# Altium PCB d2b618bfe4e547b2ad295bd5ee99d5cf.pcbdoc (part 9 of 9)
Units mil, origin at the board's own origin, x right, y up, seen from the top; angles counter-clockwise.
Board outline 5129 x 4161 mil, 8 copper layers (Top Layer, GND1, 内层2, VCC, 内层4, Inner5, GND2, Bottom Layer); 491 components, 452 nets, 2562 pads, 1124 vias.
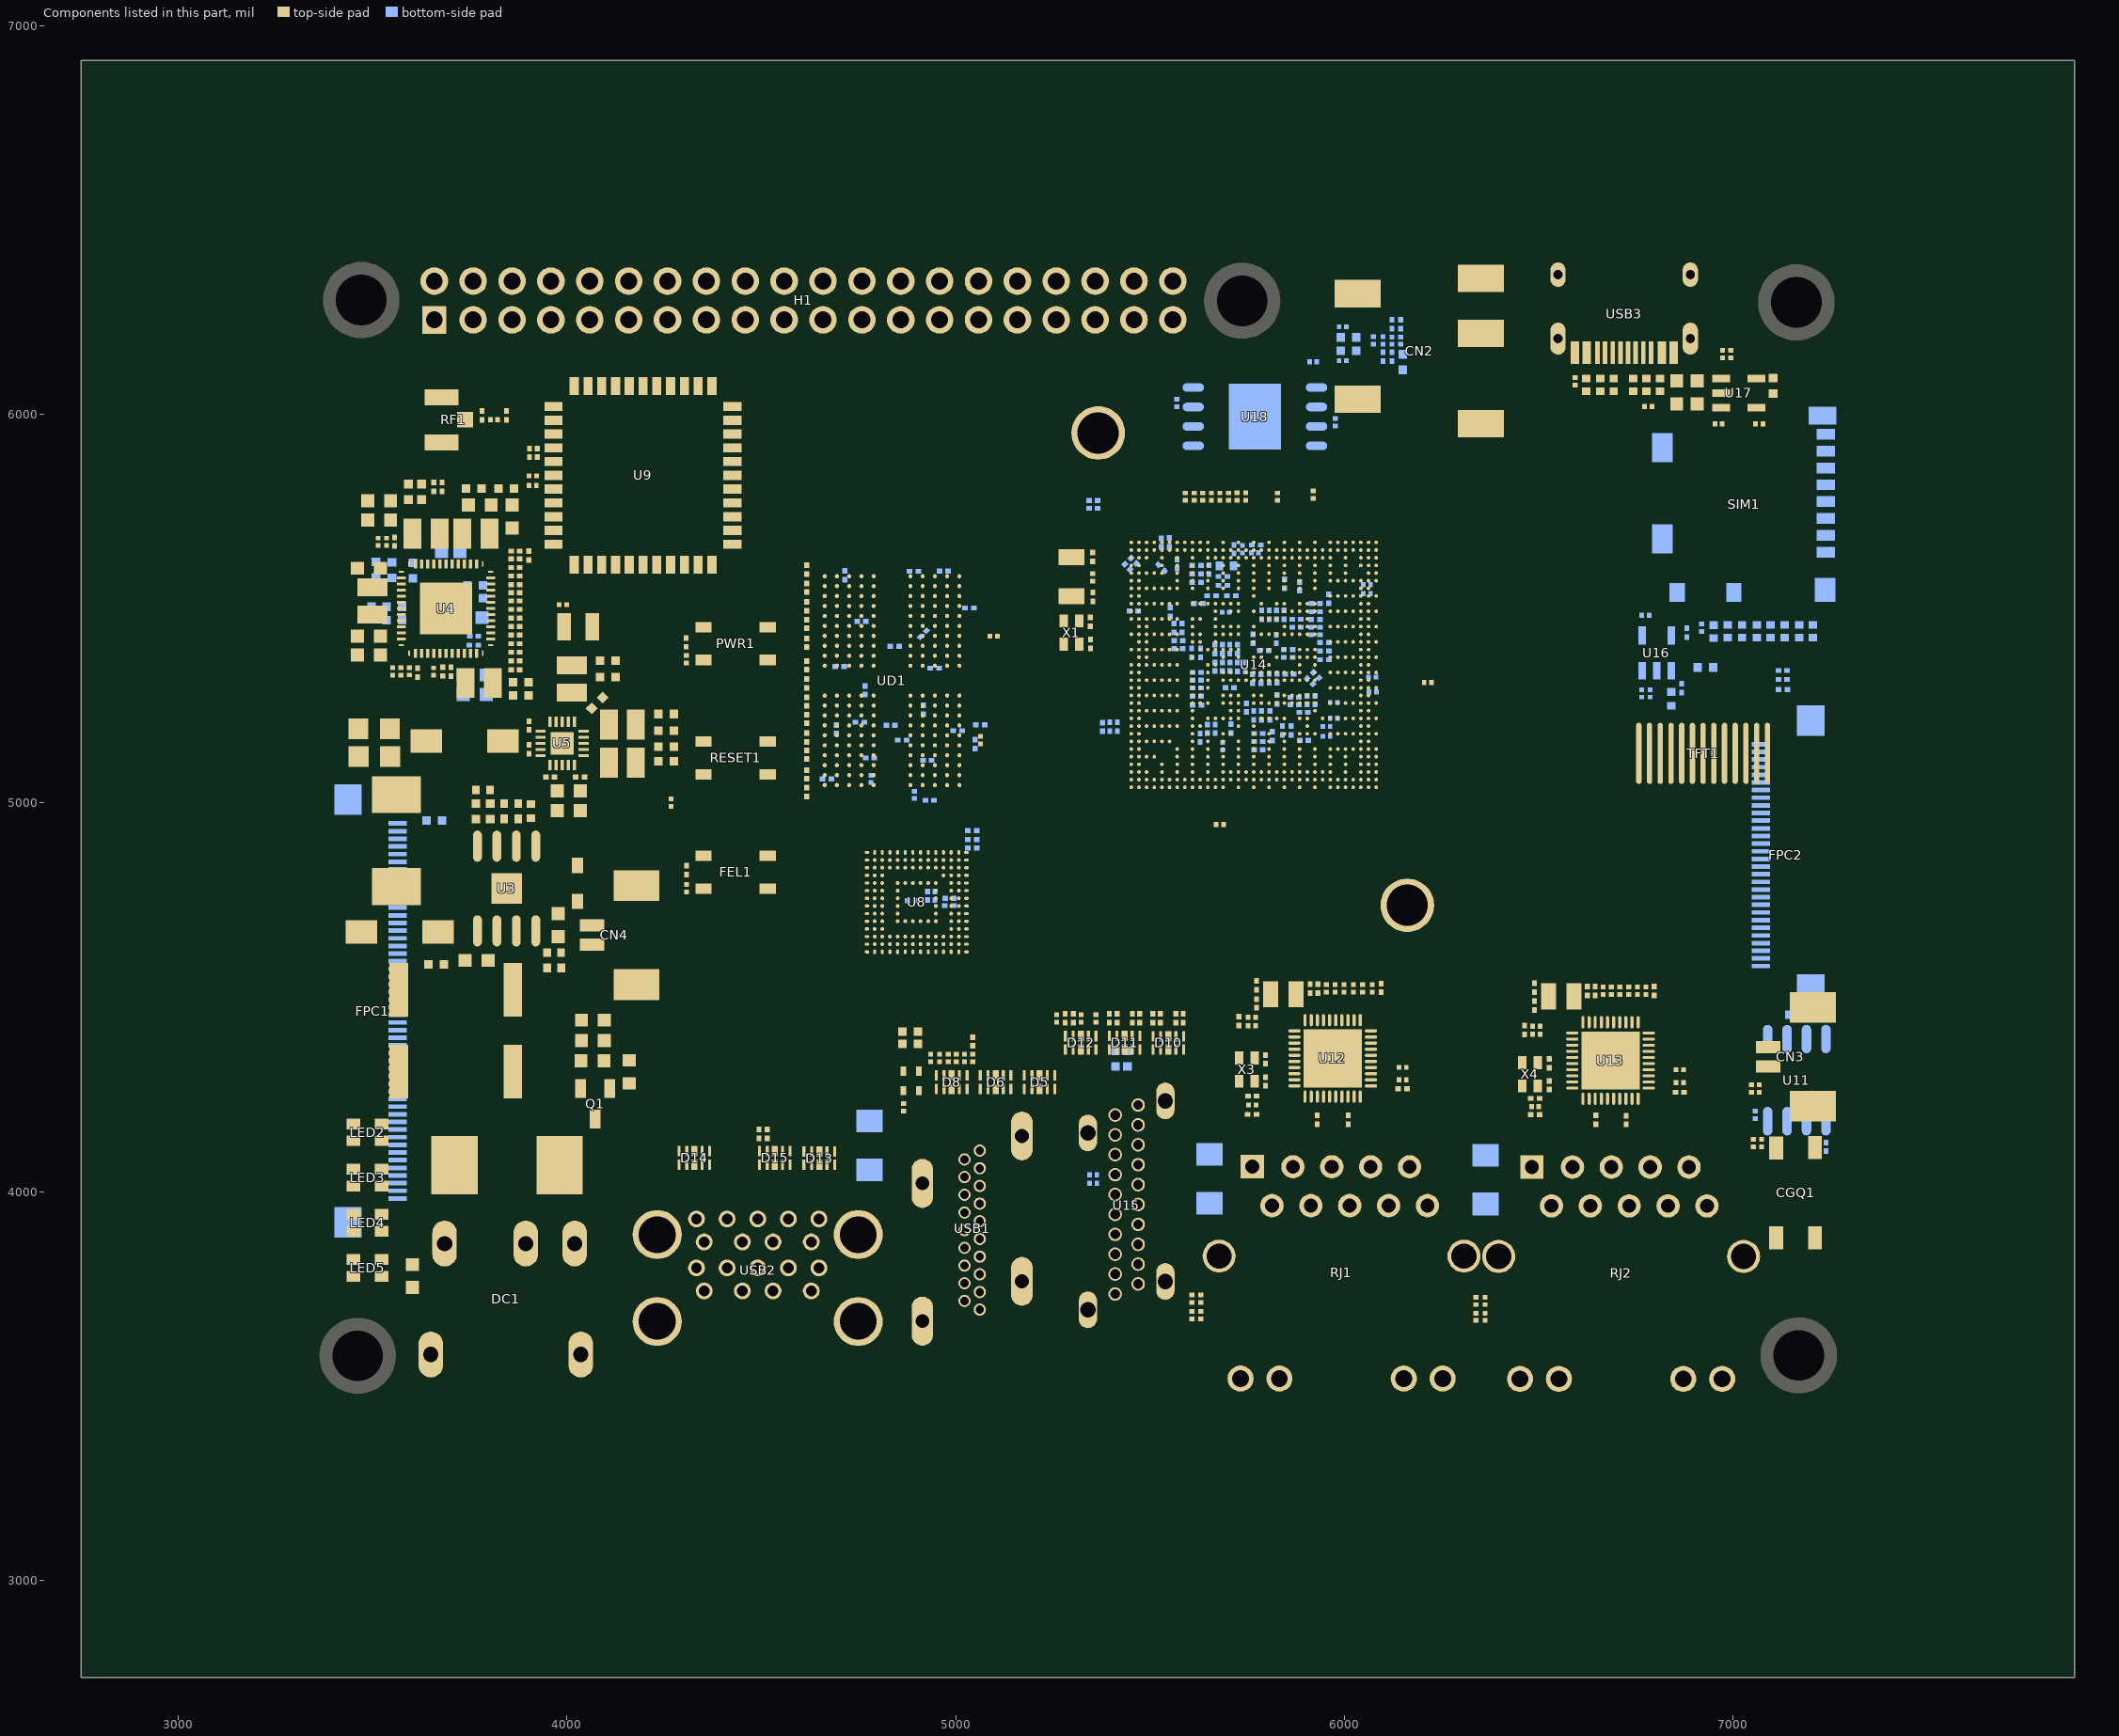
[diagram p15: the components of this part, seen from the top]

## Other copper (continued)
Inner5:
  region net VBUS: 3631.83,6301.69 3617.69,6315.83 3622.19,6322.33 3623.66,6329.06 3623.62,6344.97 3660.97,6307.62 3645.06,6307.66 3638.33,6306.19
  region net VBUS: 3707.43,6353 3707.43,6333 3699.65,6331.59 3693.85,6327.87 3682.62,6316.59 3682.62,6369.41 3693.85,6358.13 3699.65,6354.41
  region net PE15: 3792.43,6199.4 3779.91,6206.26 3777.51,6208.71 3774.15,6209.9 3765.57,6209.84 3756.16,6208.76 3747.92,6209.34 3793.68,6235.73 3789.24,6216.96 3789.17,6208.36
  region net VBUS: 3710.57,6333 3710.57,6353 3718.35,6354.41 3724.15,6358.13 3735.38,6369.41 3735.38,6316.59 3724.15,6327.87 3718.35,6331.59
  region net PE14: 3894.66,6210.17 3891.83,6207.34 3884.94,6210.05 3875.43,6209.72 3857.03,6207.62 3894.38,6244.97 3892.28,6226.57 3891.95,6217.06
  region net PE11: 3994.66,6210.17 3991.83,6207.34 3984.94,6210.05 3975.43,6209.72 3957.03,6207.62 3994.38,6244.97 3992.28,6226.57 3991.95,6217.06
  region net PE13: 4193.94,6205.89 4187.38,6206.79 4184.58,6208.9 4180.86,6209.89 4171.72,6209.61 4161.93,6208.22 4153.51,6208 4194.4,6241.43 4192.48,6230.52 4189.81,6222.22 4189.32,6214.64
  region net PE0: 4194.66,6310.17 4191.83,6307.34 4184.94,6310.05 4175.43,6309.72 4157.03,6307.62 4194.38,6344.97 4192.28,6326.57 4191.95,6317.06
  region net PE2: 4294.66,6210.17 4291.83,6207.34 4284.94,6210.05 4275.43,6209.72 4257.03,6207.62 4294.38,6244.97 4292.28,6226.57 4291.95,6217.06
  region net PE4: 4393.24,6202.59 4383.7,6206.47 4381.08,6208.76 4377.54,6209.85 4368.68,6209.66 4359.08,6208.39 4350.71,6208.55 4394.16,6238.59 4389.56,6219.58 4389.28,6211.52
  region net PE3: 4334.98,6316.15 4332.15,6318.98 4333.62,6321.58 4333.48,6324.49 4330.12,6330.98 4325.65,6337.97 4323.62,6344.97 4360.97,6307.62 4353.97,6309.65 4346.98,6314.12 4340.49,6317.48 4337.58,6317.62
  region net PE9: 4427.93,6307.1 4423.61,6308.44 4426.15,6315.44 4425.81,6325.11 4423.57,6343.56 4462.38,6307.73 4444.05,6309.65 4434.68,6309.97
  region net PE10: 4994.66,6210.17 4991.83,6207.34 4984.94,6210.05 4975.43,6209.72 4957.03,6207.62 4994.38,6244.97 4992.28,6226.57 4991.95,6217.06
  region net SDQ30: 4873.68,5531.22 4873.68,5526.72 4870.66,5525.59 4868.17,5523.11 4868.17,5534.84 4870.66,5532.36
  region net SDQ28: 4832.17,5447.21 4827.67,5447.21 4826.54,5450.23 4824.05,5452.73 4835.79,5452.73 4833.3,5450.23
  region net SDQ29: 4688.04,5459.96 4684.86,5456.77 4681.92,5458.11 4678.4,5458.11 4686.7,5466.41 4686.71,5462.89
  region net SCS0-B: 4892.9,5383.77 4889.72,5386.96 4891.05,5389.89 4891.06,5393.41 4899.36,5385.11 4895.83,5385.11
  region net SCS1-B: 4948.51,5384.38 4949.54,5391.78 4951.26,5393.84 4952.53,5396.58 4955.05,5385.12 4951.89,5385.51
  region net SCKE0-B: 4887.88,5359.26 4889.63,5367.37 4891.43,5369.31 4892.82,5371.96 4894.44,5360.5 4891.27,5360.35
  region net SCKE1-B: 4858.16,5363.72 4858.16,5368.22 4861.17,5369.36 4863.67,5371.84 4863.67,5360.11 4861.17,5362.59
  region net SDQM3: 5199.72,5346.99 5202.9,5350.17 5205.83,5348.84 5209.36,5348.84 5201.06,5340.54 5201.05,5344.06
  region net SDQS3P: 5258.47,5321.47 5254.47,5326.47 5259.98,5330.39 5263.98,5319.35 5261.24,5321.19
  region net SAB4: 4760.12,5309.96 4756.94,5306.77 4754,5308.11 4750.48,5308.11 4758.78,5316.41 4758.79,5312.89
  region net SDQ28: 5199.75,5323.62 5202.53,5327.2 5205.55,5325.93 5209.07,5325.95 5201.19,5317.26 5201.14,5320.78
  region net SCKE0-B: 5113.15,5312.71 5113.15,5317.21 5116.16,5318.35 5118.66,5320.83 5118.66,5309.1 5116.16,5311.58
  region net SDQS3N: 5258.87,5310.71 5262.4,5314.24 5267.24,5314.34 5259.33,5305.66
  region net SAB5: 4695.51,5301.38 4692.33,5304.57 4692.52,5306.84 4692.06,5309.41 4700.36,5301.11 4697.78,5301.58
  region net SDQ27: 5481.85,5303.82 5485.03,5307 5487.96,5305.67 5491.49,5305.67 5483.19,5297.37 5483.18,5300.89
  region net SDQ24: 5571.71,5305.93 5576.21,5305.93 5577.68,5304.32 5579.83,5302.96 5568.09,5302.96 5570.24,5304.32
  region net SDQ26: 5503.11,5305.6 5507.95,5307.12 5510.48,5305.57 5513.95,5305.33 5504.17,5298.85
  region net SDQ25: 5544.57,5307.14 5550.9,5307.18 5553.32,5305.71 5556.34,5304.82 5545.52,5300.29 5545.67,5303.73
  region net SCKE1-B: 5138.03,5291.68 5136.75,5299.32 5140.28,5297.99 5143.55,5298.33 5141.01,5286.87 5139.74,5289.62
  region net SAA5: 4720.94,5300.17 4724.12,5296.99 4722.79,5294.06 4722.78,5290.54 4714.48,5298.84 4718,5298.84
  region net SDQ29: 5480.29,5256.18 5480.29,5260.68 5483.3,5261.82 5485.8,5264.3 5485.8,5252.57 5483.3,5255.05
  region net SDQ31: 5544.41,5267.3 5550.27,5267.8 5552.81,5266.42 5555.91,5265.65 5545.37,5260.46
  region net SDQ30: 5502.76,5264.36 5505.94,5267.54 5508.87,5266.21 5512.4,5266.21 5504.1,5257.91 5504.09,5261.43
  region net SAA4: 4707.67,5252.74 4712.17,5252.74 4713.3,5249.72 4715.79,5247.22 4704.05,5247.22 4706.54,5249.72
  region net SAA2: 4784.39,5238.22 4780.31,5233.72 4777.55,5232.97 4774.8,5231.39 4778.88,5242.39
  region net SAA1: 5103.92,5206.61 5100.74,5203.42 5095.8,5203.1 5103.75,5211.73
  region net SDQ25: 4841.12,5603.96 4837.94,5600.77 4835,5602.11 4831.48,5602.11 4839.78,5610.41 4839.79,5606.89
  region net SDQ24: 4780.05,5579.22 4784.52,5574.72 4781.33,5573.1 4779.01,5570.55 4774.53,5581.4 4777.3,5579.9
  region net SDQ27: 4718.51,5541.57 4715.33,5538.38 4712.7,5539.41 4709.48,5539.11 4717.78,5547.41 4717.48,5544.19
  region net SCS1-A: 4973.68,5191.22 4973.68,5186.72 4970.66,5185.59 4968.17,5183.11 4968.17,5194.84 4970.66,5192.36
  region net SAA0: 5121.68,5184.22 5121.68,5179.72 5118.66,5178.59 5116.17,5176.11 5116.17,5187.84 5118.66,5185.36
  region net SDQ8: 5654.21,5145.98 5654.21,5150.48 5657.22,5151.62 5659.72,5154.1 5659.72,5142.37 5657.22,5144.85
  region net SAB4: 5525.37,5132.3 5523.25,5134.43 5524.45,5137.56 5524.06,5141.41 5532.36,5133.11 5528.5,5133.51
  region net SCS1-B: 5516.41,5146.27 5519.59,5143.09 5518.37,5138.44 5512.83,5148.61 5514.66,5147.07
  region net SCS0-B: 5480.69,5140.02 5478.59,5148.48 5482,5147.37 5485.14,5147.23 5484.12,5135.65 5482.58,5138.19
  region net SDQ14: 5700.2,5130.05 5697.02,5133.24 5698.35,5136.17 5698.36,5139.69 5706.66,5131.39 5703.13,5131.39
  region net SDQ15: 4721.68,5166.22 4721.68,5161.72 4718.66,5160.59 4716.17,5158.11 4716.17,5169.84 4718.66,5167.36
  region net SDQ14: 4690.99,5154.17 4687.89,5150.91 4684.94,5152.23 4681.42,5152.23 4689.63,5160.61 4689.65,5157.09
  region net SDQS1N: 4720.4,5128.9 4715.4,5122.97 4713.96,5126.36 4711.51,5128.48 4721.63,5134.41
  region net SDQS1P: 4731.16,5129.19 4729.28,5134.38 4731.9,5139.55 4736.14,5128.61
  region net SDQ8: 4840.94,5157.17 4844.12,5153.99 4842.79,5151.06 4842.78,5147.54 4834.48,5155.84 4838,5155.84
  region net SCS1-A: 5112.33,5149.07 5114.37,5144.75 5112.88,5142.38 5111.93,5139.4 5107.69,5150.34 5110.01,5149.13
  region net SDQ9: 5663.35,5118.23 5655.76,5117 5657.08,5120.52 5656.75,5123.81 5668.19,5121.19 5665.43,5119.93
  region net SAA4: 5518.64,5119.47 5520.89,5122.47 5523.73,5123.88 5526.4,5126.23 5524.15,5114.71 5521.78,5117.71
  region net SAA2: 5543.68,5110.62 5543.05,5114.23 5544.05,5117.26 5544.26,5120.82 5550.94,5111.16 5547.13,5111.61
  region net SDQ9: 4863.67,5119.47 4868.17,5119.47 4869.64,5117.72 4871.79,5116.22 4860.05,5116.22 4862.2,5117.72
  region net SDQM1: 4832.33,5115.38 4835.51,5118.57 4837.78,5118.37 4840.36,5118.84 4832.06,5110.54 4832.52,5113.11
  region net SAB5: 5480.3,5097.98 5480.3,5102.48 5483.31,5103.62 5485.81,5106.1 5485.81,5094.37 5483.31,5096.85
  region net SAA1: 5504.74,5091.82 5502.78,5094.09 5504.22,5097.13 5504.11,5101 5511.77,5092.1 5507.95,5092.79
  region net SDQ10: 5658.62,5090.5 5657.41,5095.65 5659,5098.1 5659.3,5101.54 5665.4,5091.51
  region net SAA5: 5558.42,5107.66 5559.36,5102.24 5557.74,5099.86 5557.37,5096.43 5551.61,5106.66
  region net SDQM1: 5622.9,5070.77 5619.72,5073.96 5621.05,5076.89 5621.06,5080.41 5629.36,5072.11 5625.83,5072.11
  region net SAA0: 5499.98,5073.72 5495.51,5078.22 5498.69,5079.85 5501.02,5082.4 5505.49,5071.55 5502.72,5073.05
  region net SDQ11: 5669.1,5067.49 5664.6,5067.49 5663.47,5070.51 5660.98,5073.01 5672.72,5073.01 5670.23,5070.51
  region net SDQ10: 4836.67,5066.47 4841.17,5066.47 4842.3,5064.09 4844.79,5062.22 4833.05,5062.22 4835.54,5064.09
  region net SDQ11: 4875.68,5059.22 4875.68,5054.72 4872.66,5053.59 4870.17,5051.11 4870.17,5062.84 4872.66,5060.36
  region net SDQ12: 5700.92,5020.22 5700.92,5015.72 5698.11,5014.59 5695.83,5012.11 5695.83,5023.84 5698.11,5021.36
  region net SDQS1N: 5680.42,4981.89 5675.42,4984.88 5674.93,4987.72 5672.91,4990.39 5684.26,4987.41
  region net SDQS1P: 5667.55,4991.38 5664.65,4987.21 5662.37,4987.36 5659.97,4986.37 5665.24,4996.86 5665.82,4993.6
  region net SDQ13: 5704.94,4983.83 5696.11,4981.36 5697.24,4984.79 5697.38,4987.89 5709.06,4987.51 5706.64,4985.83
  region net SDQ13: 4696.17,5015.21 4691.67,5015.21 4690.54,5018.23 4688.05,5020.73 4699.79,5020.73 4697.3,5018.23
  region net SDQ12: 4668.12,5019.96 4664.94,5016.77 4662,5018.11 4658.48,5018.11 4666.78,5026.41 4666.79,5022.89
  region net SDQS3P: 4755.29,5518.97 4747.42,5513.97 4744.63,5514.41 4741.52,5514.11 4749.78,5522.42 4752.05,5520.48
  region net SDQM3: 4720.12,5513.96 4716.94,5510.77 4714,5512.11 4710.48,5512.11 4718.78,5520.41 4718.79,5516.89
  region net SDQ31: 4833.67,5523.97 4838.17,5523.97 4841.79,5520.22 4830.05,5520.22
  region net SDQ26: 4699.72,5501.99 4702.9,5505.17 4705.83,5503.84 4709.36,5503.84 4701.06,5495.54 4701.05,5499.06
  region net SDQS3N: 4741,5504.59 4746.68,5503.21 4747.14,5498.11 4736,5501.8
  region net SDQ15: 5698.66,5151.53 5698.46,5157.69 5699.89,5160.16 5700.74,5163.21 5705.5,5152.48
  region net VDD-CPULFB: 3764.93,5349.86 3757.86,5356.93 3760.05,5358.93 3761.14,5361.44 3769.44,5353.14 3766.93,5352.05
  region net AP-WAKE-BT: 5776.22,5609.39 5776.22,5613.39 5779.25,5614.59 5781.73,5617.25 5781.73,5605.52 5779.25,5608.18
  region net BT-WAKE-AP: 5793.18,5600.71 5796,5597.88 5794.71,5594.88 5794.84,5591.25 5786.54,5599.55 5790.18,5599.42
  region net UART1-CTS: 5793.18,5581.04 5796,5578.21 5794.71,5575.21 5794.84,5571.58 5786.54,5579.88 5790.18,5579.75
  region net UART1-TX: 5832.55,5581.04 5835.38,5578.21 5834.09,5575.21 5834.21,5571.58 5825.91,5579.88 5829.55,5579.75
  region net UART1-RX: 5832.55,5600.71 5835.38,5597.88 5834.09,5594.88 5834.21,5591.25 5825.91,5599.55 5829.55,5599.42
  region net UART1-RTS: 5824.34,5622.14 5828.34,5622.14 5829.55,5619.11 5832.21,5616.63 5820.48,5616.63 5823.14,5619.11
  region net PE15: 5876.99,5559.81 5874.82,5551.99 5873.08,5549.99 5871.75,5547.26 5870.24,5558.76 5873.51,5558.82
  region net PE14: 5896.06,5558.52 5898.89,5561.34 5901.89,5560.05 5905.53,5560.18 5897.23,5551.88 5897.35,5555.52
  region net PE11: 5935.26,5556.91 5936.76,5561.07 5940.03,5559.98 5943.64,5560.15 5936.77,5550.63 5936.72,5554.24
  region net PE13: 5973.08,5590 5973.07,5594 5976.1,5595.21 5978.58,5597.87 5978.59,5586.13 5976.11,5588.79
  region net PE2: 6014.01,5612.4 6012.51,5619.55 6016.01,5618.18 6019.27,5618.51 6016.68,5607.28 6015.6,5610.19
  region net PE3: 6021.2,5642.14 6025.2,5642.14 6026.41,5639.11 6029.07,5636.63 6017.33,5636.63 6019.99,5639.11
  region net PE0: 6015,5590 6015,5594 6016.51,5595.57 6017.75,5597.87 6017.75,5586.13 6016.51,5588.43
  region net HSDA: 6009.04,5207.67 6012.57,5204.14 6011.2,5201.27 6011.06,5197.86 6002.76,5206.16 6006.17,5206.3
  region net HSCL: 6032.46,5198.07 6033.25,5190.21 6029.83,5191.62 6026.62,5191.37 6029.37,5202.78
  region net HHPD: 6033.65,5161.43 6033.65,5156.43 6030.65,5155.38 6028.14,5153.06 6028.14,5164.8 6030.65,5162.48
  region net HCEC: 6012.58,5153.09 6009.04,5149.56 6006.18,5150.93 6002.77,5151.07 6011.07,5159.37 6011.21,5155.95
  region net LCD0-D13: 5989.5,5073.02 5984.5,5066.8 5983.08,5070.23 5980.63,5072.31 5990.59,5078.53
  region net LCD0-D12: 5972.11,5091.57 5973.34,5099.88 5976.62,5104.39 5978.47,5093 5975.39,5092.75
  region net LCD0-HSYNC: 5910.93,5148.31 5914.47,5144.77 5913.09,5141.91 5912.95,5138.49 5904.65,5146.79 5908.07,5146.93
  region net LCD0-D20: 5957.81,5135.5 5949.92,5130.5 5944.41,5130.37 5952.3,5138.96 5954.59,5137
  region net PE10: 6113.8,5757.98 6110.98,5760.8 6112.27,5763.8 6112.14,5767.44 6120.44,5759.14 6116.8,5759.27
  region net PE9: 6134.8,5757.98 6131.98,5760.8 6133.27,5763.8 6133.14,5767.44 6141.44,5759.14 6137.8,5759.27
  region net PE4: 6156.8,5757.98 6153.98,5760.8 6155.27,5763.8 6155.14,5767.44 6163.44,5759.14 6159.8,5759.27
  region net HHPD: 5102.76,4420.5 5102.76,4415.5 5099.76,4414.45 5097.25,4412.13 5097.25,4423.87 5099.76,4421.55
  region net HSDA: 5012.76,4374.5 5012.76,4369.5 5009.76,4368.45 5007.25,4366.13 5007.25,4377.87 5009.76,4375.55
  region net HSCL: 4964.84,4379.38 4968.38,4375.84 4967,4372.98 4966.86,4369.56 4958.56,4377.86 4961.98,4378
  region net HCEC: 4942.84,4379.38 4946.38,4375.84 4945,4372.98 4944.86,4369.56 4936.56,4377.86 4939.98,4378
  region net MCSI0-D2N: 5992.22,5466.7 5989.39,5463.88 5986.39,5465.16 5982.76,5465.04 5991.06,5473.34 5990.93,5469.7
  region net MCSI0-D2P: 6006,5465 6002,5465 6000.43,5466.51 5998.13,5467.75 6009.87,5467.75 6007.57,5466.51
  region net MCSI0-D3N: 6011.41,5507.41 6008.59,5504.59 6005.89,5505.57 6002.56,5505.14 6010.86,5513.44 6010.43,5510.11
  region net MCSI0-D3P: 6018.41,5505.59 6015.59,5508.41 6015.72,5510.77 6015.14,5513.44 6023.44,5505.14 6020.77,5505.72
  region net MCSI0-SCK: 6010.93,5540.9 6003.75,5542.43 6001.58,5544.04 5998.7,5545.18 6010.12,5547.89 6009.72,5544.5
  region net MCSI0-SDA: 6032.64,5553.64 6032.64,5549.64 6030.11,5548.43 6028.14,5545.77 6028.14,5557.5 6030.11,5554.84
  region net CTP-SDA: 5812.16,4850.62 5808.62,4854.16 5810,4857.02 5810.14,4860.44 5818.44,4852.14 5815.02,4852
  region net CTP-SCK: 5821.24,4873.5 5821.24,4878.5 5824.24,4879.55 5826.75,4881.87 5826.75,4870.13 5824.24,4872.45
  region net CTP-INT: 5831.24,4891.5 5831.24,4896.5 5834.24,4897.55 5836.75,4899.87 5836.75,4888.13 5834.24,4890.45
  region net LCD0-D17: 5840.24,4909.5 5840.24,4914.5 5843.24,4915.55 5845.75,4917.87 5845.75,4906.13 5843.24,4908.45
  region net LCD0-D10: 4630.76,4675.5 4630.76,4670.5 4627.76,4669.45 4625.25,4667.13 4625.25,4678.87 4627.76,4676.55
  region net LCD0-D11: 4648.76,4659.5 4648.76,4654.5 4645.76,4653.45 4643.25,4651.13 4643.25,4662.87 4645.76,4660.55
  region net LCD0-D12: 4664.76,4643.5 4664.76,4638.5 4661.76,4637.45 4659.25,4635.13 4659.25,4646.87 4661.76,4644.55
  region net LCD0-D13: 4679.76,4626.5 4679.76,4621.5 4676.76,4620.45 4674.25,4618.13 4674.25,4629.87 4676.76,4627.55
  region net LCD0-D14: 4697.76,4610.5 4697.76,4605.5 4694.76,4604.45 4692.25,4602.13 4692.25,4613.87 4694.76,4611.55
  region net LCD0-D15: 4709.76,4592.5 4709.76,4587.5 4706.76,4586.45 4704.25,4584.13 4704.25,4595.87 4706.76,4593.55
  region net LCD0-D15: 5964.5,4905.24 5959.5,4905.24 5958.45,4908.24 5956.13,4910.75 5967.87,4910.75 5965.55,4908.24
  region net LCD0-D14: 5965.67,4932.5 5973.21,4937.5 5978.73,4937.87 5971.19,4929.02 5968.88,4931.01
  region net LCD0-D10: 5836.24,4817.5 5836.24,4822.5 5839.24,4823.55 5841.75,4825.87 5841.75,4814.13 5839.24,4816.45
  region net LCD0-D11: 5867.5,4824.24 5862.5,4824.24 5861.45,4827.24 5859.13,4829.75 5870.87,4829.75 5868.55,4827.24
  region net LCD0-D19: 4537.76,4525.5 4537.76,4520.5 4534.76,4519.45 4532.25,4517.13 4532.25,4528.87 4534.76,4526.55
  region net LCD0-D20: 4552.76,4506.5 4552.76,4501.5 4549.76,4500.45 4547.25,4498.13 4547.25,4509.87 4549.76,4507.55
  region net CTP-INT: 4341.84,4403.38 4345.38,4399.84 4344,4396.98 4343.86,4393.56 4335.56,4401.86 4338.98,4402
  region net LCD0-DE: 5885.5,4914.24 5880.5,4914.24 5879.45,4917.24 5877.13,4919.75 5888.87,4919.75 5886.55,4917.24
  region net CTP-SCK: 4316.01,4357.5 4310.05,4352.5 4304.54,4351.28 4310.5,4361.39 4312.62,4358.93
  region net CTP-SDA: 4299.01,4339.5 4293.05,4334.5 4287.54,4333.28 4293.5,4343.39 4295.62,4340.93
  region net LCD0-DE: 4281.76,4325.5 4281.76,4320.5 4278.76,4319.45 4276.25,4317.13 4276.25,4328.87 4278.76,4326.55
  region net LCD0-HSYNC: 4242.76,4290.5 4242.76,4285.5 4239.76,4284.45 4237.25,4282.13 4237.25,4293.87 4239.76,4291.55
  region net LCD0-D19: 5982.5,4847.24 5977.5,4847.24 5976.45,4850.24 5974.13,4852.75 5985.87,4852.75 5983.55,4850.24
  region net BLDO1: 5808.42,5522.69 5796.99,5525.4 5799.14,5527.74 5800.26,5529.93 5811.42,5527.48
  region net BLDO1: 5845.65,5518.58 5835.22,5522.29 5837.35,5524.54 5838.5,5526.79 5849.16,5522.87
  region net AP-WAKE-BT: 4027.02,5836.8 4024.2,5833.98 4021.2,5835.27 4017.56,5835.14 4025.86,5843.44 4025.73,5839.8
  region net BT-WAKE-AP: 4039,5842 4035,5842 4033.43,5843.51 4031.13,5844.75 4042.87,5844.75 4040.57,5843.51
  region net UART1-CTS: 4128.2,5879.02 4131.02,5876.2 4129.73,5873.2 4129.86,5869.56 4121.56,5877.86 4125.2,5877.73
  region net UART1-RTS: 4104.2,5880.02 4107.02,5877.2 4105.73,5874.2 4105.86,5870.56 4097.56,5878.86 4101.2,5878.73
  region net UART1-RX: 4082.2,5882.02 4085.02,5879.2 4083.73,5876.2 4083.86,5872.56 4075.56,5880.86 4079.2,5880.73
  region net VDD-CPULFB: 5677.27,5311 5677.27,5321 5680.24,5320.86 5682.77,5321.85 5682.77,5310.15 5680.24,5311.14
  region net VCC-LDO-RTC: 3575.46,5655.15 3564.85,5644.54 3557.94,5650.96 3569.04,5662.06
  region net BLDO1: 5595.96,5580 5602.12,5570 5598.95,5569.87 5596.62,5569.13 5590.47,5578.71
  region net BLDO1: 5858.29,5218 5850.75,5208 5845.25,5210.15 5852.8,5218.89 5855.07,5218.19
  region net MCSI0-D2N: 6886.15,4854 6886.15,4858 6888.73,4859.2 6890.77,4861.85 6890.77,4850.15 6888.73,4852.8
  region net MCSI0-D2P: 6886.15,4874 6886.15,4878 6888.73,4879.2 6890.77,4881.85 6890.77,4870.15 6888.73,4872.8
  region net MCSI0-D3N: 7017.86,4912 7017.86,4916 7020.59,4917.2 7022.77,4919.85 7022.77,4908.15 7020.59,4910.8
  region net MCSI0-D3P: 7017.86,4932.61 7017.86,4936.61 7020.44,4937.81 7022.47,4940.46 7022.47,4928.76 7020.44,4931.4
  region net MCSI0-SDA: 7005.98,5004.2 7003.53,5012.3 7007.01,5011.29 7010.23,5011.24 7009.23,4999.68 7007.79,5002.31
  region net MCSI0-SCK: 7004.89,4987.28 7006.97,4990.86 7010.12,4989.68 7013.73,4989.85 7006.23,4980.86 7006.27,4984.47
  region net UART1-TX: 4059.2,5883.02 4062.02,5880.2 4060.73,5877.2 4060.86,5873.56 4052.56,5881.86 4056.2,5881.73
  region net SAB4: 5480.98,5129.04 5478.86,5126.91 ccw(c5449.91,5103.51) 5476.23,5129.83 5479,5131.12 ccw(c5522.8,5170.86)
  region net SAA4: 5479.53,5122.47 5479.53,5119.47 ccw(c5479.53,4984.44) 5475.03,5119.4 5475.03,5122.55 ccw(c5479.53,5257.51)
  region net SAA2: 5477.88,5115.06 5480,5112.94 ccw(c5518.47,5074.47) 5478.04,5110.87 5475.81,5113.09 ccw(c5439.41,5153.53)
  region net VBUS: 3491.68,4927.32 cw(c3766.41,4652.59) 3643,5021 3643,5071 cw(c6377.09,2508.76) 3727.53,5158.32 3674.76,5176.26 3565.55,5069.15
  region net VBUS: 3413.93,4108.03 ccw(c3182.62,4339.34) 3486,4217 3511,4165.96 3486,4090 ccw(c3455.33,4066.63) 3428.07,4093.89
  region net VBUS: 3583,6277 3603,6277 ccw(c3748.72,6277) 3610.5,6230.85 3575.5,6230.85 ccw(c3437.28,6277)
  region net SAA1: 5487.1,5088.49 5487.11,5085.49 ccw(c5487.27,4950.46) 5482.61,5085.41 5482.6,5088.56 ccw(c5486.94,5223.53)
GND2:
  region net HP-DET: 5521.49,5715.73 5525.73,5711.49 5523.86,5705.56 5515.56,5713.86
  region net HPOUTL: 5486.07,5738.14 5493.14,5731.07 5490.95,5729.07 5489.86,5726.56 5481.56,5734.86 5484.07,5735.95
  region net HPOUTFB: 5462.07,5739.14 5469.14,5732.07 5466.95,5730.07 5465.86,5727.56 5457.56,5735.86 5460.07,5736.95
  region net HPOUTR: 5431,5731.76 5441,5731.76 5440.87,5728.79 5441.87,5726.25 5430.13,5726.25 5431.13,5728.79
  region net HP-DET: 5969.51,6248.27 5965.27,6252.51 5967.14,6258.44 5975.44,6250.14
  region net HBIAS: 5871,6187.24 5861,6187.24 5861.13,6190.21 5860.13,6192.75 5871.87,6192.75 5870.87,6190.21
  region net HPOUTL: 5837.93,6166.86 5830.86,6173.93 5833.05,6175.93 5834.14,6178.44 5842.44,6170.14 5839.93,6169.05
  region net HPOUTFB: 5809.93,6176.86 5802.86,6183.93 5805.05,6185.93 5806.14,6188.44 5814.44,6180.14 5811.93,6179.05
  region net HPOUTR: 5771.93,6167.86 5764.86,6174.93 5767.05,6176.93 5768.14,6179.44 5776.44,6171.14 5773.93,6170.05
Bottom Layer:
  drawing of 728 lines, arcs and shapes, not listed

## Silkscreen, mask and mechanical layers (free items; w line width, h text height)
Top Silkscreen Layer:
  text "OTG&D" at 6451.76,6394.09 h51.92 r270
  text "AUDIO" at 5884.76,6388.99 h51.92 r270
  text "GPIO" at 3597.29,6124.76 h51.92
  text "Allwinner T527" at 5554.18,5715.54 h45.43
  text "LPDDR4" at 4625.14,5632.54 h45.43
  text "ON" at 4382.85,5264.76 h51.92
  text "拆拆我的" at 4858.46,5205.25 h67.97 r90
  text "RESET" at 4310.01,4978.76 h51.92
  text "FAN" at 4122.68,4862.32 h38.94
  text "eMMC" at 4615.46,4796.13 h45.43 r90
  text "Avaota A1" at 5210,4733 h270
  text "FEL" at 4366.57,4681.76 h51.92
  text "CAN" at 7033.24,4348.57 h51.92 r90
  text "RGB LED" at 3566.76,4213.55 h51.92 r270
  text "ETH0" at 6836.29,4159.76 h51.92
  text "ETH1" at 6138.29,4155.76 h51.92
  text "IR" at 7198.85,3771.76 h51.92
  text "12VDC" at 4098.76,3726.99 h51.92 r270
  text "HDMI" at 5222.76,3666.71 h51.92 r270
  text "USB" at 4811.76,3648.43 h51.92 r270
  text "DP" at 5594.76,3590.15 h51.92 r270
Bottom Silkscreen Layer:
  circle w20: c3771,4980 r27
  circle w20: c6984,4528 r27
  text "BIOS" at 5703.22,6127.99 h29.2
  text "TFCard/JTAG" at 6797.32,6031 h38.94 r90
  text "Avaota A1" at 4897,5548 h270
  text "OV13850" at 7057.32,5244.16 h38.94 r90
  text "RGB888/LVDS/MIPI DSI/JTAG /  UART/IIC/I2S/SPI/PWM  MUX" at 3747.32,4989.1 h43.41 r90
  text "v1.4" at 7214.18,3724.24 h38.94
